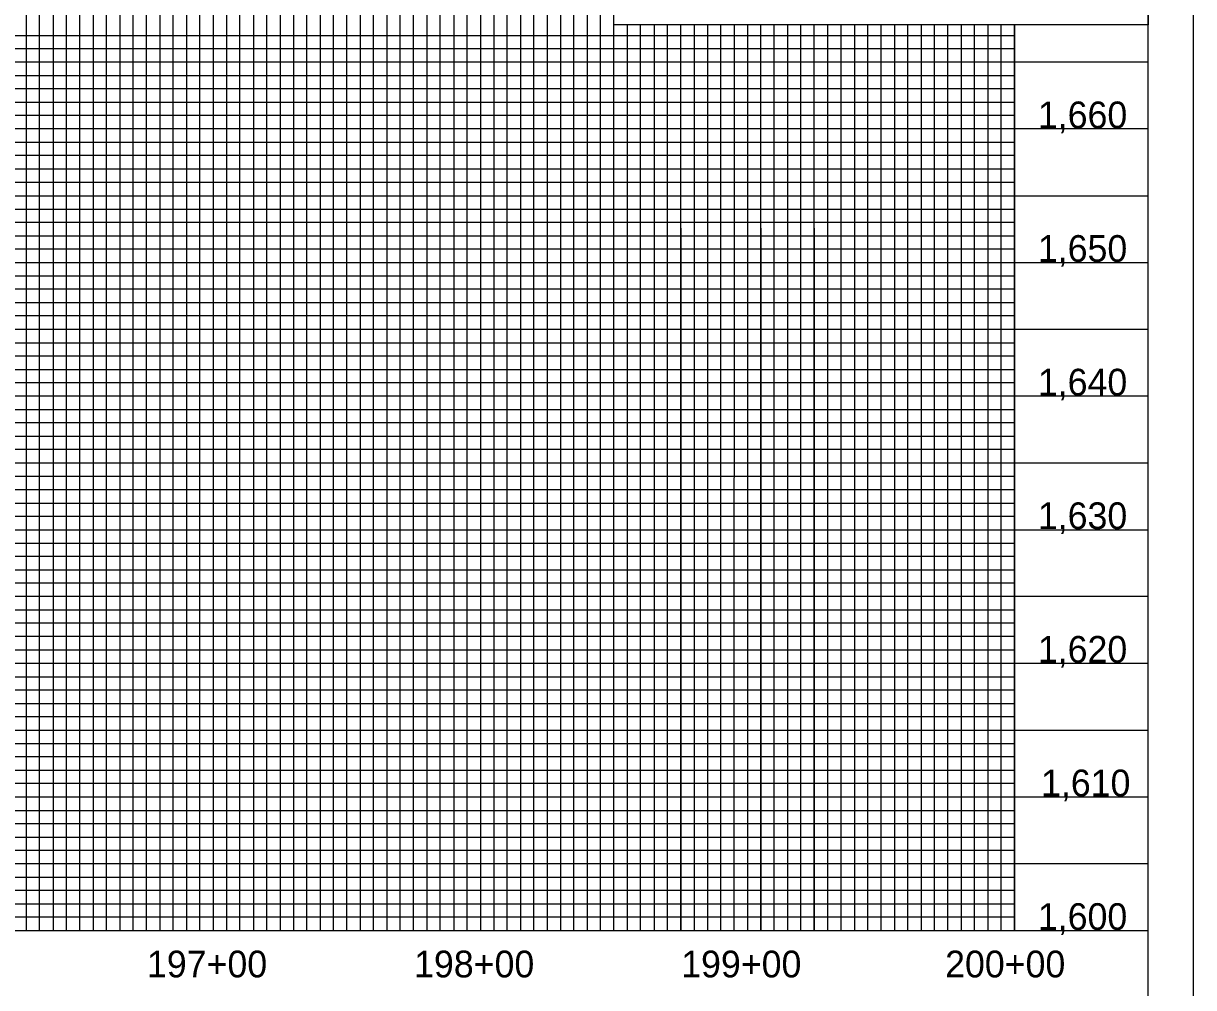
# Model space of a CAD drawing. Extents: x 505602 to 507286, y 483109 to 484209.
# Drawn here: x 506848 to 507286.1, y 483662.4 to 484023.2 of the extents above; entities that cross this region are included whole.
import ezdxf

# ---------------------------------------------------------------- set-up
doc = ezdxf.new("R2010")
doc.units = 0
for name, color, linetype in [('Exist Vertical Profile Vertical Axis Label', 7, 'Continuous'), ('Sheet Layout Profile Border Port 1', 7, 'Continuous'), ('Sheet Plot Border Outside CELL', 7, 'Continuous'), ('Sheet Profile CELL', 7, 'Continuous'), ('Sheet Profile Grid Major CELL', 7, 'Continuous'), ('Sheet Profile Grid Middle CELL', 7, 'Continuous'), ('Sheet Profile Grid Minor CELL', 7, 'Continuous'), ('Sheet Sticker Exception Certification CELL', 7, 'Continuous')]:
    doc.layers.add(name, color=color, linetype=linetype)

msp = doc.modelspace()

# ---------------------------------------------------------------- linework, layer by layer
at = {"layer": 'Sheet Layout Profile Border Port 1'}
msp.add_lwpolyline([(505819.08, 484183.71), (505819.08, 483683.71), (507219.08, 483683.71), (507219.08, 484022.66), (507069.03, 484022.66), (507069.03, 484183.71)], close=True, dxfattribs=at)
at = {"layer": 'Sheet Plot Border Outside CELL'}
msp.add_lwpolyline([(505602.08, 483108.71), (507286.08, 483108.71), (507286.08, 484208.71), (505602.08, 484208.71)], close=True, dxfattribs=at)
at = {"layer": 'Sheet Profile CELL'}
msp.add_line((505769.08, 483683.71), (507269.08, 483683.71), dxfattribs=at)
msp.add_lwpolyline([(507269.08, 484183.71), (505769.08, 484183.71), (505769.08, 483133.71), (507269.08, 483133.71)], close=True, dxfattribs=at)
at = {"layer": 'Sheet Profile Grid Major CELL'}
for points in [[(506819.08, 483683.71), (506869.08, 483683.71), (506869.08, 484183.71), (506919.08, 484183.71), (506919.08, 483683.71), (506969.08, 483683.71), (506969.08, 484183.71), (507019.08, 484183.71), (507019.08, 483683.71), (507069.08, 483683.71), (507069.08, 484183.71), (507095.38, 484183.71)], [(507219.08, 484022.66), (507219.08, 483683.71), (507269.08, 483683.71), (507269.08, 484033.71)], [(507119.08, 484022.66), (507119.08, 483683.71), (507169.08, 483683.71), (507169.08, 483683.71), (507169.08, 484022.66)], [(507269.08, 483983.71), (505769.08, 483983.71), (505769.08, 483933.71), (507269.08, 483933.71)], [(507269.08, 483883.71), (505769.08, 483883.71), (505769.08, 483833.71), (507269.08, 483833.71)], [(507269.08, 483783.71), (505769.08, 483783.71), (505769.08, 483783.71), (505769.08, 483733.71), (507269.08, 483733.71)]]:
    msp.add_lwpolyline(points, dxfattribs=at)
at = {"layer": 'Sheet Profile Grid Middle CELL'}
for points in [[(506844.08, 483683.71), (506894.08, 483683.71), (506894.08, 484183.71), (506944.08, 484183.71), (506944.08, 483683.71), (506994.08, 483683.71), (506994.08, 484183.71), (507044.08, 484183.71), (507044.08, 483683.71), (507094.08, 483683.71), (507094.08, 484022.66)], [(507094.08, 483946.51), (507094.08, 483683.71), (507144.08, 483683.71), (507144.08, 484022.66)], [(507144.08, 483946.51), (507144.08, 483683.71), (507194.08, 483683.71), (507194.08, 484022.66)], [(507269.08, 484008.71), (505769.08, 484008.71), (505769.08, 483958.71), (507094.08, 483958.71)], [(507094.08, 483958.71), (507269.08, 483958.71)], [(507269.08, 483908.71), (505769.08, 483908.71), (505769.08, 483858.71), (507269.08, 483858.71)], [(507269.08, 483808.71), (505769.08, 483808.71), (505769.08, 483758.71), (507269.08, 483758.71)], [(507269.08, 483708.71), (505769.08, 483708.71)]]:
    msp.add_lwpolyline(points, dxfattribs=at)
at = {"layer": 'Sheet Profile Grid Minor CELL'}
for p, q in [((505819.08, 484018.71), (507219.08, 484018.71)), ((507219.08, 483998.71), (505819.08, 483998.71)), ((505819.08, 483993.71), (507219.08, 483993.71)), ((507219.08, 483973.71), (505819.08, 483973.71)), ((505819.08, 483968.71), (507219.08, 483968.71)), ((507219.08, 483948.71), (505819.08, 483948.71)), ((505819.08, 483943.71), (507219.08, 483943.71)), ((507219.08, 483938.71), (505819.08, 483938.71)), ((505819.08, 483928.71), (507219.08, 483928.71)), ((507219.08, 483923.71), (505819.08, 483923.71)), ((505819.08, 483918.71), (507219.08, 483918.71)), ((507219.08, 483913.71), (505819.08, 483913.71)), ((505819.08, 483903.71), (507219.08, 483903.71)), ((507219.08, 483898.71), (505819.08, 483898.71)), ((505819.08, 483893.71), (507219.08, 483893.71)), ((507219.08, 483888.71), (505819.08, 483888.71)), ((505819.08, 483878.71), (507219.08, 483878.71)), ((507219.08, 483873.71), (505819.08, 483873.71)), ((505819.08, 483868.71), (507219.08, 483868.71)), ((507219.08, 483863.71), (505819.08, 483863.71)), ((505819.08, 483853.71), (507219.08, 483853.71)), ((507219.08, 483848.71), (505819.08, 483848.71)), ((505819.08, 483843.71), (507219.08, 483843.71)), ((507219.08, 483838.71), (505819.08, 483838.71)), ((505819.08, 483828.71), (507219.08, 483828.71)), ((507219.08, 483823.71), (505819.08, 483823.71)), ((505819.08, 483818.71), (507219.08, 483818.71)), ((507219.08, 483813.71), (505819.08, 483813.71)), ((505819.08, 483803.71), (507219.08, 483803.71)), ((507219.08, 483798.71), (505819.08, 483798.71)), ((507219.08, 483793.71), (505819.08, 483793.71)), ((507219.08, 483788.71), (505819.08, 483788.71)), ((505819.08, 483778.71), (507219.08, 483778.71)), ((507219.08, 483773.71), (505819.08, 483773.71)), ((505819.08, 483768.71), (507219.08, 483768.71)), ((507219.08, 483763.71), (505819.08, 483763.71)), ((505819.08, 483753.71), (507219.08, 483753.71)), ((507219.08, 483748.71), (505819.08, 483748.71)), ((505819.08, 483743.71), (507219.08, 483743.71)), ((507219.08, 483738.71), (505819.08, 483738.71)), ((505819.08, 483728.71), (507219.08, 483728.71)), ((507219.08, 483723.71), (505819.08, 483723.71)), ((505819.08, 483718.71), (507219.08, 483718.71)), ((507219.08, 483713.71), (505819.08, 483713.71)), ((505819.08, 483703.71), (507219.08, 483703.71)), ((507219.08, 483698.71), (505819.08, 483698.71)), ((505819.08, 483693.71), (507219.08, 483693.71))]:
    msp.add_line(p, q, dxfattribs=at)
for points in [[(506849.08, 484183.71), (506849.08, 483683.71), (506854.08, 483683.71), (506854.08, 484183.71)], [(506859.08, 484183.71), (506859.08, 483683.71), (506864.08, 483683.71), (506864.08, 484183.71)], [(506874.08, 484183.71), (506874.08, 483683.71), (506879.08, 483683.71), (506879.08, 484183.71)], [(506884.08, 484183.71), (506884.08, 483683.71), (506889.08, 483683.71), (506889.08, 484183.71)], [(506899.08, 484183.71), (506899.08, 483683.71), (506904.08, 483683.71), (506904.08, 484183.71)], [(506909.08, 484183.71), (506909.08, 483683.71), (506914.08, 483683.71), (506914.08, 484183.71)], [(506924.08, 484183.71), (506924.08, 483683.71), (506929.08, 483683.71), (506929.08, 484183.71)], [(506934.08, 484183.71), (506934.08, 483683.71), (506939.08, 483683.71), (506939.08, 484183.71)], [(506949.08, 484183.71), (506949.08, 483683.71), (506954.08, 483683.71), (506954.08, 484183.71)], [(506959.08, 484183.71), (506959.08, 483683.71)], [(506959.08, 483683.71), (506964.08, 483683.71), (506964.08, 484183.71)], [(506974.08, 484183.71), (506974.08, 483683.71), (506979.08, 483683.71), (506979.08, 484183.71)], [(506984.08, 484183.71), (506984.08, 483683.71), (506989.08, 483683.71), (506989.08, 484183.71)], [(506999.08, 484183.71), (506999.08, 483683.71), (507004.08, 483683.71), (507004.08, 484183.71)], [(507009.08, 484183.71), (507009.08, 483683.71), (507014.08, 483683.71), (507014.08, 484183.71)], [(507024.08, 484183.71), (507024.08, 483683.71), (507029.08, 483683.71), (507029.08, 484183.71)], [(507034.08, 484183.71), (507034.08, 483683.71), (507039.08, 483683.71), (507039.08, 484183.71)], [(507049.08, 484183.71), (507049.08, 483683.71), (507054.08, 483683.71), (507054.08, 484183.71)], [(507059.08, 484183.71), (507059.08, 483683.71), (507064.08, 483683.71), (507064.08, 484183.71)], [(507074.08, 484022.66), (507074.08, 483683.71), (507079.08, 483683.71), (507079.08, 484022.66)], [(507084.08, 484022.66), (507084.08, 483683.71), (507089.08, 483683.71), (507089.08, 484022.66)], [(507099.08, 484022.66), (507099.08, 483683.71), (507099.08, 483683.71), (507104.08, 483683.71), (507109.08, 483683.71), (507109.08, 484022.66)], [(507104.08, 484022.66), (507104.08, 483683.71)], [(507114.07, 484022.66), (507113.98, 483683.76), (507118.98, 483683.76), (507124.08, 483683.71), (507124.08, 484022.66)], [(507124.08, 483946.51), (507124.08, 483683.71), (507129.08, 483683.71), (507129.08, 484022.66)], [(507134.08, 484022.66), (507134.08, 483683.71), (507139.08, 483683.71), (507139.08, 484022.66)], [(507149.08, 484022.66), (507149.08, 483683.71), (507154.08, 483683.71), (507154.08, 484022.66)], [(507159.08, 484022.66), (507159.08, 483683.71), (507164.08, 483683.71), (507164.08, 484022.66)], [(507174.08, 484022.66), (507174.08, 483683.71), (507179.08, 483683.71), (507179.08, 484022.66)], [(507184.08, 484022.66), (507184.08, 483683.71), (507189.08, 483683.71), (507189.08, 484022.66)], [(507199.08, 484022.66), (507199.08, 483683.71), (507204.08, 483683.71), (507204.08, 484022.66)], [(507209.08, 484022.66), (507209.08, 483683.71), (507214.08, 483683.71), (507214.08, 484022.66)], [(507219.08, 484013.71), (505819.08, 484013.71), (505819.08, 484003.71), (507219.08, 484003.71)], [(507219.08, 483988.71), (505819.08, 483988.71), (505819.08, 483978.71), (507219.08, 483978.71)], [(507219.08, 483963.71), (505819.08, 483963.71), (505819.08, 483953.71), (507219.08, 483953.71)], [(507219.08, 483688.71), (505819.08, 483688.71)]]:
    msp.add_lwpolyline(points, dxfattribs=at)
at = {"layer": 'Sheet Sticker Exception Certification CELL'}
for p, q in [((507069.03, 484022.66), (507069.03, 484046.16)), ((507069.03, 484022.66), (507069.03, 484046.16)), ((507269.07, 484046.15), (507269.07, 484022.65)), ((507269.07, 484046.15), (507269.07, 484022.65)), ((507269.07, 484022.66), (507069.03, 484022.66)), ((507269.07, 484022.66), (507069.03, 484022.66))]:
    msp.add_line(p, q, dxfattribs=at)

# ---------------------------------------------------------------- texts
at = {"layer": 'Exist Vertical Profile Vertical Axis Label'}
for s, p in [('1,660', (507227.78, 483983.96)), ('1,650', (507227.78, 483933.96)), ('1,640', (507227.78, 483883.96)), ('1,630', (507227.78, 483833.96)), ('1,620', (507227.78, 483783.96)), ('1,610', (507228.97, 483733.96)), ('1,600', (507227.78, 483683.96)), ('197+00', (506894.26, 483666.21)), ('198+00', (506994.26, 483666.21)), ('199+00', (507094.26, 483666.21)), ('200+00', (507193.06, 483666.21))]:
    msp.add_text(s, height=10, dxfattribs=at).set_placement(p)

doc.saveas('drawing.dxf')
